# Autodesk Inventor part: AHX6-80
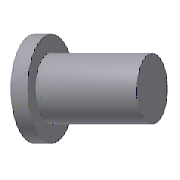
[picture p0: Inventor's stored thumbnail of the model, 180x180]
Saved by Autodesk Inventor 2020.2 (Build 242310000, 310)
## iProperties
IsCustomPart: 1
Manager: www.cadconsulting.pl
Company: Fabian Stasiak CAD Consulting
Created: 2014-02
Part Number: AHX6-80
Material: DIN 1.2344
Description: Core Pin
Document SubType Name: Modeling
Standard: ISO
Designer: F.Stasiak
Standard Revision: 1
Manufacturer: DME
Language: pl-PL
Size Designation: 6-80
Categories: <MemberInstance><Categories><Category DisplayName="Forma wtryskowa" InternalName="349578f2-f4d4-4954-8c09-8e99297a61c0" Mnemonic="MOLD"><Category DisplayName="W
Mass: 5.34093 g
Surface Area: 25.2527 cm^2
Volume: 5.34093 cm^3
Density: 7.85 g/cm^3
Appearance: Stal
Catalog Web Link: www.expertbooks.pl
Author: F.Stasiak
Subject: Zbiór ćwiczeń. Autodesk Inventor 2020. Kurs Professional
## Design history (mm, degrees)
sketch "Sketch1"
  geometry: L1 (0, 0)-(6, 0); L2 (6, 0)-(6, 5); L3 (6, 5)-(3, 5); L4 (3, 5)-(3, 80); L5 (3, 80)-(0, 80); L6 (0, 0)-(0, 80); L7 (0, 96)-(0, -16) reference; 1 further point
  constraints: 12 end point, 3 parallel, 2 perpendicular, 1 coincident
  dimensions: "d5" = 5 distance between parallel lines of L1 L3 (= k); "d28" = 80 distance between parallel lines of L5 L1 (= l1); "d44" = 6 diameter of L4 L7 (= d1); "d45" = 12 diameter of L2 L7 (= d2)
revolve "Revolution1" sketch "Sketch1" stored, may be unused: angle "d7" = 90 deg
fillet "Fillet1" dims "d27" = 0.5 (= R)
workplane "Work Plane1"
sketch "Sketch2"
  geometry: 2 further points
  constraints: 1 vertical alignment
  dimensions: "d31" = 2.5 distance of point (0, -2.5) point (0, 0) (= 0.5 x k)
hole "Anti_Rotary Hole" sketch "Sketch2" at (0, 0) diameter "d32" = 1.05 (= Anti_Rotary_D); stored, may be unused: countersink angle "d36" = 90 deg, drill point angle "d38" = 118 deg; dims "d33" = 6, "d34" = 4, "d35" = 2, "d37" = 1.575 (= 1.5 x Anti_Rotary_D)
sketch "Sketch3"
  geometry: L1 (-3.3, 5.011)-(-3.3, -5.011); A1 r 6 centre (0, 0) between (-3.3, 5.011) and (-3.3, -5.011) reference; 1 further point
  constraints: 2 end point, 2 point on circle, 1 vertical
  dimensions: "d39" = 3.3 distance from line of point (0, 0) L1 (= Anti_Rotary_P)
extrude "Anti_Rotary Plane" cut sketch "Sketch3" extent not by distance; stored distance "d40" = 5.3 (computed from k); taper "d41" = 0 deg
body "Solid1"
other parameters: "d1" = 6 [user parameter; used in 1 equation term], "d2" = 12 [user parameter; used in 1 equation term], "k" = 5 [user parameter; used in 3 equation terms], "l1" = 80 [user parameter; used in 1 equation term], "d20" = 0, "d21" = 0, "R" = 0.5 [user parameter; used in 1 equation term], "d29" = 0, "d30" = 0, "Anti_Rotary_P" = 3.3 [user parameter; used in 1 equation term], "Anti_Rotary_D" = 1.05 [user parameter; used in 2 equation terms], "d42" = 0, "d43" = 0, "IsARPlane" = 0 [user parameter], "IsARHole" = 0 [user parameter]
